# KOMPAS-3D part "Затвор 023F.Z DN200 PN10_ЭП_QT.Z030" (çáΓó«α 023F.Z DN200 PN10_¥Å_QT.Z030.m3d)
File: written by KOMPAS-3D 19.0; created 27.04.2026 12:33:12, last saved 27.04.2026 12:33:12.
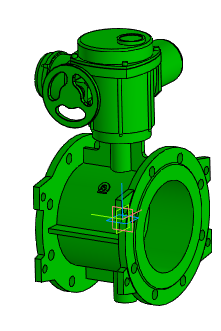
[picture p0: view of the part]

Document properties: Полное имя файла: Затвор 023F.Z DN200 PN10 + электропривод QT.Z030.a3d

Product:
- Part/product: Затвор 023F.Z DN200 PN10_ЭП_QT.Z030
    Масса: 86.1777
  - Body: Тело 1
      Масса: 86.5527

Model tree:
1. Операция без истории:1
